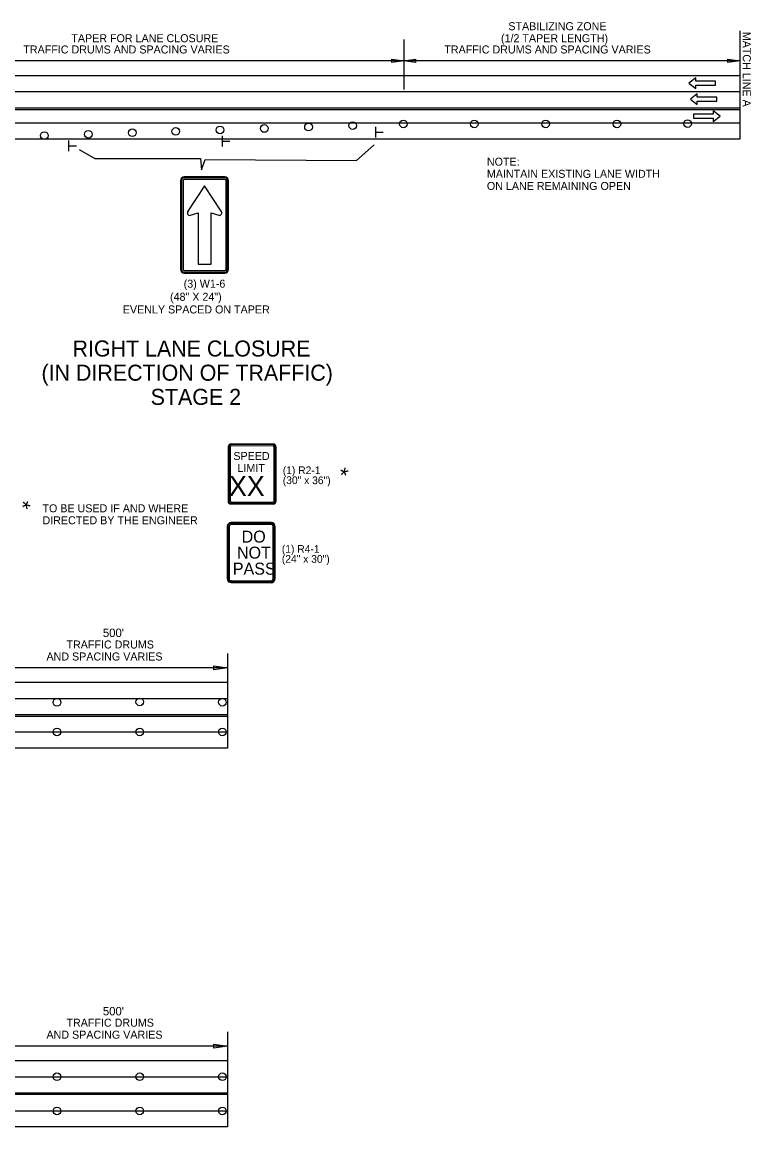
# Model space of a CAD drawing. Extents: x 1930579 to 1938013, y 596452 to 597673.
# Drawn here: x 1934532 to 1935078, y 596702 to 597530 of the extents above; entities that cross this region are included whole.
import ezdxf

# ---------------------------------------------------------------- set-up
doc = ezdxf.new("R2010")
doc.units = 0
for name, color, linetype in [('Default', 7, 'Continuous'), ('P_TC_Signs_Permanent', 7, 'Continuous'), ('R_Annotation', 7, 'Continuous'), ('R_Striping', 7, 'Continuous')]:
    doc.layers.add(name, color=color, linetype=linetype)

msp = doc.modelspace()

# ---------------------------------------------------------------- linework, layer by layer
at = {"layer": 'Default'}
for p, q in [((1935069.92, 597523.93), (1935069.92, 597466.19)), ((1934818.18, 597517.31), (1934818.18, 597480.01)), ((1934818.18, 597501.43), (1934450.97, 597501.43)), ((1934809.32, 597500.1), (1934809.32, 597502.76)), ((1934809.32, 597502.76), (1934818.18, 597501.43)), ((1934818.18, 597501.43), (1934809.32, 597500.1)), ((1934818.18, 597501.43), (1934827.05, 597502.76)), ((1935069.92, 597501.43), (1934818.18, 597501.43)), ((1934827.05, 597500.1), (1934818.18, 597501.43)), ((1934827.05, 597502.76), (1934827.05, 597500.1)), ((1935061.06, 597500.1), (1935061.06, 597502.76)), ((1935061.06, 597502.76), (1935069.92, 597501.43)), ((1935069.92, 597501.43), (1935061.06, 597500.1)), ((1935069.92, 597490.19), (1933755.41, 597490.19)), ((1935069.92, 597478.19), (1933755.41, 597478.19)), ((1935069.92, 597465.96), (1933755.41, 597465.96)), ((1935069.92, 597464.81), (1933755.41, 597464.81)), ((1935069.92, 597466.19), (1935069.92, 597442.63)), ((1935069.92, 597454.63), (1933755.41, 597454.63)), ((1934797.19, 597443.96), (1934797.19, 597451.94)), ((1934797.31, 597447.93), (1934802.76, 597447.93)), ((1935069.92, 597442.63), (1933755.41, 597442.63)), ((1934567.27, 597433.69), (1934567.27, 597441.67)), ((1934682.23, 597437.18), (1934682.23, 597445.16)), ((1934682.35, 597441.15), (1934687.8, 597441.15)), ((1934567.39, 597437.66), (1934572.84, 597437.66)), ((1934686.11, 597057.24), (1934686.11, 597010.74)), ((1934686.11, 597046.45), (1934521.71, 597046.45)), ((1934675.8, 597044.9), (1934675.8, 597047.99)), ((1934675.8, 597047.99), (1934686.11, 597046.45)), ((1934686.11, 597046.45), (1934675.8, 597044.9)), ((1934686.11, 597035.46), (1933682.42, 597035.46)), ((1933682.42, 597023.46), (1934686.11, 597023.46)), ((1934686.11, 597011.23), (1933682.42, 597011.23)), ((1934686.11, 597010.08), (1933682.42, 597010.08)), ((1934686.11, 597010.74), (1934686.11, 596986.31)), ((1933682.42, 596998.31), (1934686.11, 596998.53)), ((1934686.11, 596986.31), (1933682.42, 596986.31)), ((1934686.11, 596773.75), (1934686.11, 596727.25)), ((1934686.11, 596762.96), (1934521.71, 596762.96)), ((1934675.8, 596761.41), (1934675.8, 596764.5)), ((1934675.8, 596764.5), (1934686.11, 596762.96)), ((1934686.11, 596762.96), (1934675.8, 596761.41)), ((1934686.11, 596751.97), (1933682.42, 596751.97)), ((1933682.42, 596739.97), (1934686.11, 596739.97)), ((1934686.11, 596727.74), (1933682.42, 596727.74)), ((1934686.11, 596726.59), (1933682.42, 596726.59)), ((1934686.11, 596727.25), (1934686.11, 596702.39)), ((1933682.42, 596714.39), (1934686.11, 596714.39)), ((1934686.11, 596702.39), (1933682.42, 596702.39))]:
    msp.add_line(p, q, dxfattribs=at)
for centre in [(1934746.8, 597451.82), (1934779.95, 597452.92), (1934817.9, 597454.14), (1934870.98, 597454.14), (1934924.45, 597454.14), (1934977.92, 597454.15), (1935030.83, 597454.41), (1934548.84, 597445.39), (1934581.82, 597446.43), (1934614.81, 597447.48), (1934647.34, 597448.51), (1934680.49, 597449.61), (1934713.65, 597450.71), (1934558.32, 597020.59), (1934620.32, 597020.91), (1934682.32, 597020.68), (1934558.32, 596998.42), (1934620.32, 596998.42), (1934682.32, 596998.42), (1934558.32, 596739.96), (1934620.32, 596739.96), (1934682.32, 596739.96), (1934558.32, 596714.39), (1934620.32, 596714.39), (1934682.32, 596714.39)]:
    msp.add_circle(centre, 2.87, dxfattribs=at)
at = {"layer": 'P_TC_Signs_Permanent'}
for p, q in [((1934684.07, 597414.37), (1934653.69, 597414.37)), ((1934684.07, 597413.62), (1934653.69, 597413.62)), ((1934650.88, 597411.56), (1934650.88, 597345.18)), ((1934651.63, 597411.56), (1934651.63, 597345.18)), ((1934652.75, 597411.56), (1934652.75, 597345.18)), ((1934684.07, 597412.49), (1934653.69, 597412.49)), ((1934685, 597345.18), (1934685, 597411.56)), ((1934686.13, 597345.18), (1934686.13, 597411.56)), ((1934686.88, 597345.18), (1934686.88, 597411.56)), ((1934653.69, 597344.24), (1934684.07, 597344.24)), ((1934653.69, 597343.12), (1934684.07, 597343.12)), ((1934653.69, 597342.37), (1934684.07, 597342.37)), ((1934686.59, 597212.04), (1934686.49, 597171.54)), ((1934687.15, 597212.04), (1934687.05, 597171.54)), ((1934688.09, 597212.04), (1934687.99, 597171.54)), ((1934720.34, 597214.21), (1934688.84, 597214.29)), ((1934720.34, 597213.65), (1934688.84, 597213.73)), ((1934720.34, 597212.71), (1934688.84, 597212.79)), ((1934720.99, 597171.46), (1934721.09, 597211.96)), ((1934721.92, 597171.46), (1934722.03, 597211.96)), ((1934722.49, 597171.45), (1934722.59, 597211.95)), ((1934688.73, 597169.85), (1934720.23, 597169.77)), ((1934688.73, 597169.29), (1934720.23, 597169.21)), ((1934688.74, 597170.79), (1934720.23, 597170.71)), ((1934685.87, 597152.35), (1934685.78, 597113.35)), ((1934686.47, 597152.35), (1934686.38, 597113.35)), ((1934687.37, 597152.35), (1934687.28, 597113.35)), ((1934718.88, 597155.27), (1934688.88, 597155.35)), ((1934718.88, 597154.67), (1934688.88, 597154.75)), ((1934718.88, 597153.77), (1934688.88, 597153.85)), ((1934720.28, 597113.27), (1934720.37, 597152.27)), ((1934721.18, 597113.27), (1934721.27, 597152.27)), ((1934721.78, 597113.26), (1934721.87, 597152.26)), ((1934688.77, 597111.85), (1934718.77, 597111.77)), ((1934688.77, 597110.95), (1934718.77, 597110.87)), ((1934688.77, 597110.35), (1934718.77, 597110.27))]:
    msp.add_line(p, q, dxfattribs=at)
for points in [[(1934681.32, 597388.63), (1934668.88, 597407.62), (1934656.47, 597388.62)], [(1934658.25, 597385.67), (1934664, 597387.39), (1934664, 597349.12), (1934673.75, 597349.12), (1934673.75, 597387.39), (1934679.5, 597385.63)]]:
    msp.add_lwpolyline(points, dxfattribs=at)
for centre, radius, start, end in [((1934653.69, 597411.56), 2.81, 90, 180), ((1934653.69, 597411.56), 2.06, 90, 180), ((1934684.07, 597411.56), 2.81, 360, 90), ((1934684.07, 597411.56), 2.06, 360, 90), ((1934653.69, 597411.56), 0.938, 90, 180), ((1934684.07, 597411.56), 0.938, 360, 90), ((1934657.76, 597387.36), 1.76, 146.59943, 285.96908), ((1934593.67, 597429.62), 75, 326.59943, 326.85697), ((1934680, 597387.36), 1.8, 254.03093, 33.47548), ((1934744.06, 597429.72), 75, 213.2286, 213.47548), ((1934653.69, 597345.18), 2.81, 180, 270), ((1934653.69, 597345.18), 2.06, 180, 270), ((1934653.69, 597345.18), 0.937, 180, 270), ((1934684.07, 597345.18), 2.81, 270, 360), ((1934684.07, 597345.18), 2.06, 270, 360), ((1934684.07, 597345.18), 0.938, 270, 360), ((1934688.84, 597212.04), 2.25, 89.85705, 179.85705), ((1934688.84, 597212.04), 1.69, 89.85705, 179.85705), ((1934688.84, 597212.04), 0.75, 89.85705, 179.85705), ((1934720.34, 597211.96), 2.25, 359.85705, 89.85705), ((1934720.34, 597211.96), 1.69, 359.85705, 89.85705), ((1934720.34, 597211.96), 0.75, 359.85705, 89.85705), ((1934688.74, 597171.54), 2.25, 179.85705, 269.85705), ((1934688.74, 597171.54), 1.69, 179.85705, 269.85705), ((1934688.74, 597171.54), 0.75, 179.85705, 269.85705), ((1934720.24, 597171.46), 1.69, 269.85705, 359.85705), ((1934720.24, 597171.46), 0.75, 269.85705, 359.85705), ((1934720.24, 597171.46), 2.25, 269.85705, 359.85705), ((1934688.87, 597152.35), 3, 89.85705, 179.85705), ((1934688.87, 597152.35), 2.4, 89.85705, 179.85705), ((1934688.87, 597152.35), 1.5, 89.85705, 179.85705), ((1934718.87, 597152.27), 3, 359.85705, 89.85705), ((1934718.87, 597152.27), 2.4, 359.85705, 89.85705), ((1934718.87, 597152.27), 1.5, 359.85705, 89.85705), ((1934688.78, 597113.35), 3, 179.85705, 269.85705), ((1934688.78, 597113.35), 2.4, 179.85705, 269.85705), ((1934688.78, 597113.35), 1.5, 179.85705, 269.85705), ((1934718.78, 597113.27), 2.4, 269.85705, 359.85705), ((1934718.78, 597113.27), 1.5, 269.85705, 359.85705), ((1934718.78, 597113.27), 3, 269.85705, 359.85705)]:
    msp.add_arc(centre, radius, start, end, dxfattribs=at)
at = {"layer": 'R_Annotation'}
msp.add_lwpolyline([(1934574.95, 597435.05), (1934586.76, 597428.1), (1934665.96, 597428.1), (1934666.66, 597419.75), (1934669.44, 597427.4), (1934782.69, 597426.71), (1934795.89, 597438.53)], dxfattribs=at)
at = {"layer": 'R_Striping'}
for points in [[(1935037.08, 597488.56), (1935031.88, 597484.56), (1935037.08, 597480.56), (1935037.08, 597483.06), (1935051.79, 597483.06), (1935051.79, 597486.06), (1935037.08, 597486.06)], [(1935038.13, 597476.78), (1935032.94, 597472.78), (1935038.13, 597468.78), (1935038.13, 597471.28), (1935052.84, 597471.28), (1935052.84, 597474.28), (1935038.13, 597474.28)], [(1935050.05, 597456.05), (1935055.25, 597460.05), (1935050.05, 597464.05), (1935050.05, 597461.55), (1935035.34, 597461.55), (1935035.34, 597458.55), (1935050.05, 597458.55)]]:
    msp.add_lwpolyline(points, close=True, dxfattribs=at)

# ---------------------------------------------------------------- texts
at = {"layer": 'Default'}
for s, height, rotation, p in [('STABILIZING ZONE', 6, 360, (1934896.55, 597524.36)), ('TAPER FOR LANE CLOSURE', 6, 360, (1934569.07, 597515.36)), ('(1/2 TAPER LENGTH)', 6, 360, (1934891.03, 597515.36)), ('MATCH LINE A', 5.9996, 270, (1935072.23, 597523.18)), ('TRAFFIC DRUMS AND SPACING VARIES', 6, 360, (1934533.1, 597506.93)), ('TRAFFIC DRUMS AND SPACING VARIES', 6, 360, (1934848.58, 597506.93)), ('RIGHT LANE CLOSURE', 12, 360, (1934569.93, 597279.8)), ('(IN DIRECTION OF TRAFFIC)', 12, 360, (1934546.68, 597261.68)), ('STAGE 2', 12, 360, (1934628.51, 597243.56)), ("500'", 6.336, 360, (1934592.72, 597069.54)), ('TRAFFIC DRUMS ', 6, 360, (1934565.43, 597060.96)), ('AND SPACING VARIES', 6, 360, (1934550.43, 597051.96)), ("500'", 6.336, 360, (1934592.72, 596785.97)), ('TRAFFIC DRUMS ', 6, 360, (1934565.43, 596777.51)), ('AND SPACING VARIES', 6, 360, (1934550.43, 596768.51))]:
    msp.add_text(s, height=height, rotation=rotation, dxfattribs=at).set_placement(p)
at = {"layer": 'P_TC_Signs_Permanent'}
for s, height, rotation, p in [('SPEED', 6, 359.85705, (1934690.49, 597202.28)), ('LIMIT', 6, 359.85705, (1934693.56, 597193.28)), ('XX', 15, 359.85705, (1934687.2, 597175.29)), ('DO', 9, 359.85705, (1934696.67, 597140.33)), ('NOT', 9, 359.81669, (1934693.16, 597128.34)), ('PASS', 9, 359.85705, (1934690.08, 597116.34))]:
    msp.add_text(s, height=height, rotation=rotation, dxfattribs=at).set_placement(p)
at = {"layer": 'R_Annotation'}
for s, height, rotation, p in [('NOTE:', 6, 360, (1934880.47, 597422.84)), ('MAINTAIN EXISTING LANE WIDTH', 6, 360, (1934880.47, 597413.73)), ('ON LANE REMAINING OPEN', 6, 360, (1934880.47, 597404.62)), ('(3) W1-6', 6, 0.00754, (1934653.27, 597331.37)), ('(48" X 24")', 6, 0.00754, (1934643.04, 597321.57)), ('EVENLY SPACED ON TAPER', 6, 0.00754, (1934607.63, 597312.07)), ('(30" x 36")', 5.76, 359.85705, (1934727.52, 597184.2)), ('(1) R2-1', 5.76, 359.85705, (1934727.54, 597191.69)), ('*', 12, 134.85705, (1934782.01, 597197.41)), ('*', 12, 45, (1934539.25, 597160.1)), ('TO BE USED IF AND WHERE', 6, 360, (1934547.43, 597163.04)), ('DIRECTED BY THE ENGINEER', 6, 360, (1934547.43, 597154.04)), ('(1) R4-1', 5.76, 359.85705, (1934726.83, 597132.75)), ('(24" x 30")', 5.76, 359.85705, (1934726.81, 597125.26))]:
    msp.add_text(s, height=height, rotation=rotation, dxfattribs=at).set_placement(p)

doc.saveas('drawing.dxf')
